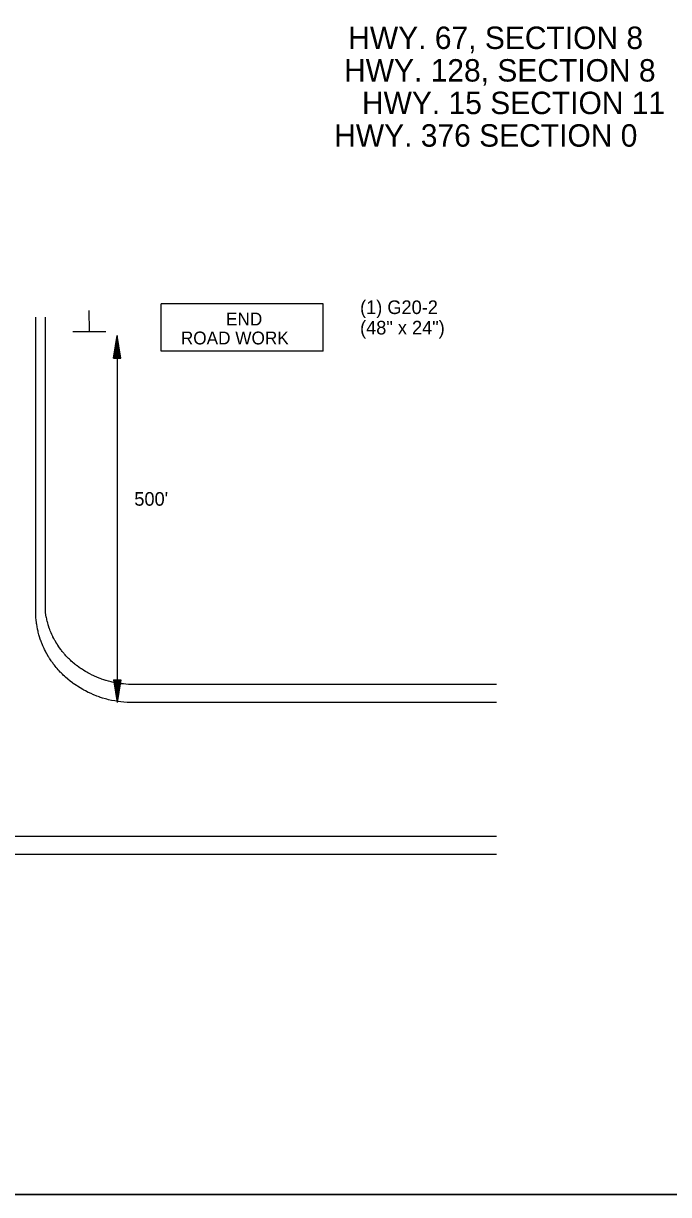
# Model space of a CAD drawing. Extents: x 1416408 to 1429341, y 372694 to 383211.
# Drawn here: x 1417480 to 1417967, y 376066 to 376949 of the extents above; entities that cross this region are included whole.
import ezdxf

# ---------------------------------------------------------------- set-up
doc = ezdxf.new("R2010")
doc.units = 0
for name, color, linetype in [('Default', 7, 'Continuous'), ('DSN_DRFT_Junk-No-Plot', 7, 'Continuous'), ('R_Dimension', 7, 'Continuous'), ('R_MOT', 7, 'Continuous'), ('R_Proposed Road', 7, 'Continuous')]:
    doc.layers.add(name, color=color, linetype=linetype)

msp = doc.modelspace()

# ---------------------------------------------------------------- linework, layer by layer
at = {"layer": 'Default'}
msp.add_lwpolyline([(1416407.68, 377826.46), (1416407.68, 376066.46), (1419127.68, 376066.46), (1419127.68, 377826.46)], close=True, dxfattribs=at)
at = {"layer": 'DSN_DRFT_Junk-No-Plot'}
msp.add_lwpolyline([(1416407.68, 377826.46), (1419127.68, 377826.46), (1419127.68, 376066.46), (1416407.68, 376066.46)], close=True, dxfattribs=at)
at = {"layer": 'R_Dimension'}
for p, q in [((1417548.26, 376696.67), (1417551.02, 376713.76)), ((1417551.02, 376713.76), (1417551.02, 376437.13)), ((1417553.77, 376696.67), (1417551.02, 376713.76)), ((1417548.72, 376696.67), (1417551.02, 376710.9)), ((1417549.19, 376696.67), (1417551.02, 376707.96)), ((1417549.65, 376696.67), (1417551.02, 376705.12)), ((1417553.31, 376696.67), (1417551.02, 376710.9)), ((1417552.84, 376696.67), (1417551.02, 376707.96)), ((1417552.38, 376696.67), (1417551.02, 376705.12)), ((1417548.26, 376696.67), (1417553.77, 376696.67)), ((1417550.12, 376696.67), (1417551.02, 376702.22)), ((1417550.58, 376696.67), (1417551.02, 376699.37)), ((1417551.92, 376696.67), (1417551.02, 376702.22)), ((1417551.45, 376696.67), (1417551.02, 376699.37)), ((1417548.26, 376454.21), (1417551.02, 376437.13)), ((1417548.26, 376454.21), (1417553.77, 376454.21)), ((1417548.72, 376454.21), (1417551.02, 376439.98)), ((1417549.19, 376454.21), (1417551.02, 376442.92)), ((1417549.65, 376454.21), (1417551.02, 376445.76)), ((1417550.12, 376454.21), (1417551.02, 376448.66)), ((1417550.58, 376454.21), (1417551.02, 376451.51)), ((1417553.77, 376454.21), (1417551.02, 376437.13)), ((1417551.92, 376454.21), (1417551.02, 376448.66)), ((1417552.84, 376454.21), (1417551.02, 376442.92)), ((1417553.31, 376454.21), (1417551.02, 376439.98)), ((1417552.38, 376454.21), (1417551.02, 376445.76)), ((1417551.45, 376454.21), (1417551.02, 376451.51))]:
    msp.add_line(p, q, dxfattribs=at)
at = {"layer": 'R_MOT'}
for p, q in [((1417530.15, 376716.93), (1417530.08, 376732.68)), ((1417706.4, 376737.67), (1417584.32, 376737.67)), ((1417584.32, 376702.02), (1417584.32, 376737.67)), ((1417706.4, 376702.02), (1417706.4, 376737.67)), ((1417542.5, 376716.65), (1417517.68, 376716.54)), ((1417706.4, 376702.02), (1417584.32, 376702.02))]:
    msp.add_line(p, q, dxfattribs=at)
at = {"layer": 'R_Proposed Road'}
for p, q in [((1417489.79, 376661.77), (1417489.79, 376727.54)), ((1417497.15, 376661.76), (1417497.15, 376727.54))]:
    msp.add_line(p, q, dxfattribs=at)
for points in [[(1417563.32, 376437.13), (1417560.96, 376437.16), (1417558.61, 376437.27), (1417556.26, 376437.44), (1417553.92, 376437.69), (1417551.73, 376437.98), (1417551.58, 376438), (1417549.26, 376438.39), (1417546.96, 376438.84), (1417544.67, 376439.36), (1417543.37, 376439.69), (1417542.4, 376439.95), (1417540.15, 376440.61), (1417537.92, 376441.33), (1417537.73, 376441.4), (1417535.73, 376442.12), (1417533.56, 376442.98), (1417533.24, 376443.11), (1417531.42, 376443.9), (1417529.44, 376444.82), (1417529.31, 376444.88), (1417527.24, 376445.92), (1417526.11, 376446.52), (1417525.2, 376447.03), (1417523.21, 376448.19), (1417523.14, 376448.23), (1417521.25, 376449.42), (1417520.46, 376449.94), (1417519.34, 376450.7), (1417518, 376451.65), (1417517.48, 376452.04), (1417515.75, 376453.36), (1417515.66, 376453.43), (1417513.89, 376454.88), (1417513.66, 376455.07), (1417512.17, 376456.38), (1417511.73, 376456.78), (1417511.33, 376457.14), (1417510.5, 376457.92), (1417509.92, 376458.48), (1417508.89, 376459.52), (1417508.24, 376460.19), (1417507.33, 376461.17), (1417506.67, 376461.9), (1417505.83, 376462.86), (1417505.2, 376463.61), (1417504.39, 376464.59), (1417503.82, 376465.32), (1417503.01, 376466.37), (1417502.53, 376467.03), (1417501.7, 376468.19), (1417501.32, 376468.73), (1417500.44, 376470.04), (1417500.18, 376470.44), (1417499.64, 376471.3), (1417499.25, 376471.93), (1417499.12, 376472.15), (1417498.13, 376473.86), (1417498.13, 376473.86), (1417497.2, 376475.57), (1417497.07, 376475.82), (1417496.34, 376477.28), (1417496.08, 376477.8), (1417495.54, 376478.99), (1417495.16, 376479.82), (1417494.79, 376480.69), (1417494.32, 376481.86), (1417494.11, 376482.4), (1417493.54, 376483.93), (1417493.47, 376484.11), (1417492.9, 376485.82), (1417492.83, 376486.02), (1417492.37, 376487.53), (1417492.2, 376488.13), (1417491.9, 376489.24), (1417491.63, 376490.26), (1417491.47, 376490.94), (1417491.15, 376492.4), (1417491.1, 376492.65), (1417490.77, 376494.36), (1417490.73, 376494.56), (1417490.49, 376496.07), (1417490.39, 376496.73), (1417490.26, 376497.78), (1417490.13, 376498.9), (1417490.07, 376499.49), (1417489.94, 376501.09), (1417489.94, 376501.2), (1417489.84, 376502.9), (1417489.83, 376503.28), (1417489.8, 376504.61), (1417489.79, 376505.47), (1417489.79, 376506.32), (1417489.79, 376508.03), (1417489.79, 376509.74), (1417489.79, 376511.45), (1417489.79, 376513.15), (1417489.79, 376514.86), (1417489.79, 376516.57), (1417489.79, 376518.28), (1417489.79, 376519.99), (1417489.79, 376521.7), (1417489.79, 376523.41), (1417489.79, 376525.11), (1417489.79, 376526.82), (1417489.79, 376528.53), (1417489.79, 376530.24), (1417489.79, 376531.95), (1417489.79, 376533.66), (1417489.79, 376535.36), (1417489.79, 376537.07), (1417489.79, 376538.78), (1417489.79, 376540.49), (1417489.79, 376542.2), (1417489.79, 376543.91), (1417489.79, 376545.61), (1417489.79, 376547.32), (1417489.79, 376549.03), (1417489.79, 376550.74), (1417489.79, 376552.45), (1417489.79, 376554.16), (1417489.79, 376555.87), (1417489.79, 376557.57), (1417489.79, 376559.28), (1417489.79, 376560.99), (1417489.79, 376562.7), (1417489.79, 376564.41), (1417489.79, 376566.12), (1417489.79, 376567.82), (1417489.79, 376569.53), (1417489.79, 376571.24), (1417489.79, 376572.95), (1417489.79, 376574.66), (1417489.79, 376576.37), (1417489.79, 376578.08), (1417489.79, 376579.78), (1417489.79, 376581.49), (1417489.79, 376583.2), (1417489.79, 376584.91), (1417489.79, 376586.62), (1417489.79, 376588.33), (1417489.79, 376590.03), (1417489.79, 376591.74), (1417489.79, 376593.45), (1417489.79, 376595.16), (1417489.79, 376596.87), (1417489.79, 376598.58), (1417489.79, 376600.29), (1417489.79, 376601.99), (1417489.79, 376603.7), (1417489.79, 376605.41), (1417489.79, 376607.12), (1417489.79, 376608.83), (1417489.79, 376610.54), (1417489.79, 376612.24), (1417489.79, 376613.95), (1417489.79, 376615.66), (1417489.79, 376617.37), (1417489.79, 376619.08), (1417489.79, 376620.79), (1417489.79, 376622.5), (1417489.79, 376624.2), (1417489.79, 376625.91), (1417489.79, 376627.62), (1417489.79, 376629.33), (1417489.79, 376631.04), (1417489.79, 376632.75), (1417489.79, 376634.45), (1417489.79, 376636.16), (1417489.79, 376637.87), (1417489.79, 376639.58), (1417489.79, 376641.29), (1417489.79, 376642.14), (1417489.79, 376643), (1417489.79, 376644.71), (1417489.79, 376646.41), (1417489.79, 376648.12), (1417489.79, 376649.83), (1417489.79, 376651.54), (1417489.79, 376653.25), (1417489.79, 376654.96), (1417489.79, 376656.66), (1417489.79, 376657.92), (1417489.79, 376658.37), (1417489.79, 376660.07), (1417489.79, 376661.77)], [(1417563.32, 376450.8), (1417561.43, 376450.82), (1417559.55, 376450.89), (1417557.67, 376451.02), (1417555.79, 376451.19), (1417554.03, 376451.39), (1417553.92, 376451.41), (1417552.05, 376451.68), (1417550.19, 376452), (1417548.34, 376452.37), (1417547.29, 376452.6), (1417546.5, 376452.78), (1417544.67, 376453.25), (1417542.85, 376453.76), (1417542.69, 376453.81), (1417541.04, 376454.33), (1417539.25, 376454.94), (1417538.99, 376455.03), (1417537.48, 376455.6), (1417535.83, 376456.26), (1417535.73, 376456.31), (1417533.99, 376457.06), (1417533.04, 376457.5), (1417532.27, 376457.87), (1417530.58, 376458.72), (1417530.52, 376458.75), (1417528.91, 376459.62), (1417528.22, 376460.01), (1417527.26, 376460.56), (1417526.1, 376461.27), (1417525.64, 376461.56), (1417524.13, 376462.54), (1417524.05, 376462.6), (1417522.49, 376463.68), (1417522.29, 376463.82), (1417520.96, 376464.81), (1417520.56, 376465.11), (1417520.2, 376465.39), (1417519.46, 376465.99), (1417518.93, 376466.41), (1417517.99, 376467.21), (1417517.4, 376467.72), (1417516.56, 376468.47), (1417515.95, 376469.03), (1417515.17, 376469.78), (1417514.57, 376470.36), (1417513.81, 376471.12), (1417513.26, 376471.69), (1417512.49, 376472.52), (1417512.03, 376473.03), (1417511.22, 376473.95), (1417510.85, 376474.38), (1417509.99, 376475.42), (1417509.73, 376475.74), (1417509.19, 376476.42), (1417508.8, 376476.93), (1417508.67, 376477.11), (1417507.66, 376478.48), (1417507.66, 376478.48), (1417506.71, 376479.87), (1417506.57, 376480.07), (1417505.8, 376481.26), (1417505.53, 376481.69), (1417504.94, 376482.66), (1417504.54, 376483.35), (1417504.13, 376484.07), (1417503.6, 376485.04), (1417503.36, 376485.49), (1417502.71, 376486.76), (1417502.64, 376486.91), (1417501.96, 376488.35), (1417501.88, 376488.52), (1417501.33, 376489.79), (1417501.11, 376490.31), (1417500.73, 376491.24), (1417500.4, 376492.12), (1417500.18, 376492.71), (1417499.74, 376493.96), (1417499.67, 376494.17), (1417499.2, 376495.65), (1417499.15, 376495.82), (1417498.77, 376497.14), (1417498.62, 376497.71), (1417498.39, 376498.63), (1417498.15, 376499.62), (1417498.04, 376500.14), (1417497.75, 376501.55), (1417497.73, 376501.65), (1417497.47, 376503.17), (1417497.41, 376503.5), (1417497.24, 376504.7), (1417497.14, 376505.47), (1417497.14, 376506.32), (1417497.14, 376508.03), (1417497.14, 376509.74), (1417497.14, 376511.45), (1417497.14, 376513.15), (1417497.14, 376514.86), (1417497.14, 376516.57), (1417497.14, 376518.28), (1417497.14, 376519.99), (1417497.14, 376521.7), (1417497.14, 376523.41), (1417497.14, 376525.11), (1417497.14, 376526.82), (1417497.14, 376528.53), (1417497.14, 376530.24), (1417497.14, 376531.95), (1417497.14, 376533.66), (1417497.14, 376535.36), (1417497.14, 376537.07), (1417497.14, 376538.78), (1417497.14, 376540.49), (1417497.14, 376542.2), (1417497.14, 376543.91), (1417497.14, 376545.61), (1417497.14, 376547.32), (1417497.14, 376549.03), (1417497.14, 376550.74), (1417497.14, 376552.45), (1417497.14, 376554.16), (1417497.14, 376555.87), (1417497.14, 376557.57), (1417497.14, 376559.28), (1417497.14, 376560.99), (1417497.14, 376562.7), (1417497.14, 376564.41), (1417497.14, 376566.12), (1417497.14, 376567.82), (1417497.14, 376569.53), (1417497.14, 376571.24), (1417497.14, 376572.95), (1417497.14, 376574.66), (1417497.14, 376576.37), (1417497.14, 376578.08), (1417497.14, 376579.78), (1417497.14, 376581.49), (1417497.14, 376583.2), (1417497.14, 376584.91), (1417497.14, 376586.62), (1417497.14, 376588.33), (1417497.14, 376590.03), (1417497.14, 376591.74), (1417497.14, 376593.45), (1417497.14, 376595.16), (1417497.14, 376596.87), (1417497.14, 376598.58), (1417497.14, 376600.29), (1417497.14, 376601.99), (1417497.14, 376603.7), (1417497.14, 376605.41), (1417497.14, 376607.12), (1417497.14, 376608.83), (1417497.14, 376610.54), (1417497.14, 376612.24), (1417497.14, 376613.95), (1417497.14, 376615.66), (1417497.14, 376617.37), (1417497.14, 376619.08), (1417497.14, 376620.79), (1417497.14, 376622.5), (1417497.14, 376624.2), (1417497.14, 376625.91), (1417497.14, 376627.62), (1417497.14, 376629.33), (1417497.14, 376631.04), (1417497.14, 376632.75), (1417497.14, 376634.45), (1417497.14, 376636.16), (1417497.14, 376637.87), (1417497.14, 376639.58), (1417497.14, 376641.29), (1417497.14, 376642.14), (1417497.14, 376643), (1417497.14, 376644.71), (1417497.14, 376646.41), (1417497.14, 376648.12), (1417497.14, 376649.83), (1417497.14, 376651.54), (1417497.14, 376653.25), (1417497.14, 376654.96), (1417497.14, 376656.66), (1417497.14, 376657.92), (1417497.14, 376658.37), (1417497.14, 376660.07), (1417497.15, 376661.76), (1417497.15, 376661.77)], [(1417836.9, 376450.8), (1417829.86, 376450.8), (1417811.47, 376450.8), (1417793.09, 376450.8), (1417774.71, 376450.8), (1417756.33, 376450.8), (1417737.95, 376450.8), (1417719.56, 376450.8), (1417701.18, 376450.8), (1417682.8, 376450.8), (1417667.7, 376450.8), (1417667.69, 376450.8), (1417664.42, 376450.8), (1417646.04, 376450.8), (1417627.66, 376450.8), (1417609.27, 376450.8), (1417590.89, 376450.8), (1417572.51, 376450.8), (1417563.32, 376450.8)], [(1417836.9, 376437.13), (1417829.86, 376437.13), (1417811.47, 376437.13), (1417793.09, 376437.13), (1417774.71, 376437.13), (1417756.33, 376437.13), (1417737.95, 376437.13), (1417719.56, 376437.13), (1417701.18, 376437.13), (1417682.8, 376437.13), (1417667.7, 376437.13), (1417667.69, 376437.13), (1417664.42, 376437.13), (1417646.04, 376437.13), (1417627.66, 376437.13), (1417609.27, 376437.13), (1417590.89, 376437.13), (1417572.51, 376437.13), (1417563.32, 376437.13)], [(1417836.9, 376336.33), (1417811.47, 376336.33), (1417793.09, 376336.33), (1417774.71, 376336.33), (1417756.33, 376336.33), (1417737.95, 376336.33), (1417719.56, 376336.33), (1417701.18, 376336.33), (1417682.8, 376336.33), (1417667.7, 376336.33), (1417667.69, 376336.33), (1417664.42, 376336.33), (1417646.04, 376336.33), (1417627.66, 376336.33), (1417609.27, 376336.33), (1417590.89, 376336.33), (1417572.51, 376336.33), (1417554.13, 376336.33), (1417535.75, 376336.33), (1417517.36, 376336.33), (1417498.98, 376336.33), (1417480.6, 376336.33), (1417471.41, 376336.33)], [(1417836.9, 376322.66), (1417811.47, 376322.66), (1417793.09, 376322.66), (1417774.71, 376322.66), (1417756.33, 376322.66), (1417737.95, 376322.66), (1417719.56, 376322.66), (1417701.18, 376322.66), (1417682.8, 376322.66), (1417667.7, 376322.66), (1417667.69, 376322.66), (1417664.42, 376322.66), (1417646.04, 376322.66), (1417627.66, 376322.66), (1417609.27, 376322.66), (1417590.89, 376322.66), (1417572.51, 376322.66), (1417554.13, 376322.66), (1417535.75, 376322.66), (1417517.36, 376322.66), (1417498.98, 376322.66), (1417480.6, 376322.66), (1417471.41, 376322.66)]]:
    msp.add_lwpolyline(points, dxfattribs=at)

# ---------------------------------------------------------------- texts
at = {"layer": 'Default'}
for s, p in [('HWY. 67, SECTION 8', (1417725.22, 376929.64)), ('HWY. 128, SECTION 8', (1417722.07, 376905.11)), ('HWY. 15 SECTION 11', (1417735.55, 376880.57)), ('HWY. 376 SECTION 0', (1417714.64, 376856.04))]:
    msp.add_text(s, height=16.8914, dxfattribs=at).set_placement(p)
at = {"layer": 'R_Dimension'}
msp.add_text("500'", height=10.251, dxfattribs=at).set_placement((1417564.04, 376585.5))
at = {"layer": 'R_MOT'}
for s, height, p in [('(1) G20-2', 10.251, (1417734.12, 376729.93)), ('END', 9.687, (1417633.11, 376721.35)), ('(48" x 24")', 10.2497, (1417734.12, 376714.56)), ('ROAD WORK', 9.687, (1417599.09, 376707.04))]:
    msp.add_text(s, height=height, dxfattribs=at).set_placement(p)

doc.saveas('drawing.dxf')
